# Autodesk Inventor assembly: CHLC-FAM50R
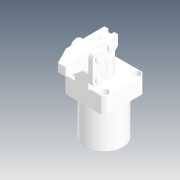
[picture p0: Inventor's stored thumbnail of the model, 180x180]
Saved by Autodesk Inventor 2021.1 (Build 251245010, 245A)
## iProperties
Created: 2019-04
Part Number: CHLC-FAM50R
Description: STEP AP214
Document SubType Name: Assembly
Designer: user
Title: CHLC-FAM50R.STEP
Revision Number: ÈÎºÎ
Sending System: SolidWorks 2016
Preprocessor: SwSTEP 2.0
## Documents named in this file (10)
- D:\Vault_2016\Projekty\Clamptek\Hydraulic\CHLC\CHLC-50\Inventor\CHLC-FAM50R\CHLC-FAM50R.iam
- D:\Vault_2016\Projekty\Clamptek\Hydraulic\CHLC\CHLC-50\Inventor\CHLC-FAM50R\CHLC-FAM50-±¾Ìå.ipt
- D:\Vault_2016\Projekty\Clamptek\Hydraulic\CHLC\CHLC-50\Inventor\CHLC-FAM50R\CHLC-50-01.ipt
- D:\Vault_2016\Projekty\Clamptek\Hydraulic\CHLC\CHLC-50\Inventor\CHLC-FAM50R\CHLC-50-02.ipt
- D:\Vault_2016\Projekty\Clamptek\Hydraulic\CHLC\CHLC-50\Inventor\CHLC-FAM50R\CHLC-50-03.ipt
- D:\Vault_2016\Projekty\Clamptek\Hydraulic\CHLC\CHLC-50\Inventor\CHLC-FAM50R\CHLC-50-04.ipt
- D:\Vault_2016\Projekty\Clamptek\Hydraulic\CHLC\CHLC-50\Inventor\CHLC-FAM50R\CHLC-50-06.ipt
- D:\Vault_2016\Projekty\Clamptek\Hydraulic\CHLC\CHLC-50\Inventor\CHLC-FAM50R\CHLC-50-09.ipt
- D:\Vault_2016\Projekty\Clamptek\Hydraulic\CHLC\CHLC-50\Inventor\CHLC-FAM50R\M6LS.ipt
- D:\Vault_2016\Projekty\Clamptek\Hydraulic\CHLC\CHLC-50\Inventor\CHLC-FAM50R\YAKUAI.ipt
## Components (17 placed, 17 different names)
1. CHLC-FAM50-±¾Ìå_1
2. CHLC-50-01_2
3. CHLC-50-02_3
4. CHLC-50-03_4
5. CHLC-50-04_5
6. CHLC-50-06_6
7. CHLC-50-09_7
8. M6LS_8
9. YAKUAI_9
10. CHLC-50-03_10
11. CHLC-50-04_11
12. CHLC-50-06_12
13. CHLC-50-06_13
14. CHLC-50-06_14
15. CHLC-50-06_15
16. CHLC-50-06_16
17. M6LS_17
